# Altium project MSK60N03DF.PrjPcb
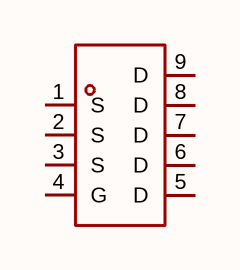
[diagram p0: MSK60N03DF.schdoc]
1 sheet, 1 parts. Net scope: global (net labels, ports and power ports of the same name join across sheets).

## Sheet MSK60N03DF.schdoc
size 127 x 101 mm

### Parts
Q?  msk60n03df  [DFN-8_L3.0-W3.0-P0.65-BL]  (value not drawn)

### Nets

Not connected (* = marked no-connect by the designer): Q? 1(S) 2(S) 3(S) 4(G) 5(D) 6(D) 7(D) 8(D) 9(D)

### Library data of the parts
Q? = msk60n03df: 数量:1个N沟道;漏源电压(Vdss):30V;连续漏极电流(Id):60A;导通电阻(RDS(on)):6mΩ@10V;耗散功率(Pd):59W;阈值电压(Vgs(th)):2.5V;; Manufacturer: MSKSEMI(美森科); AddInBom: yes; ModelId: 8b850663669847e9b39b8fc804d68d4b; ModelName: DFN-8_L3.0-W3.0-H0.7-P0.65; ModelTransform: 118.8974,118.11,0,90,0,0,0,0,0; Number: 1个N沟道; Drain to Source Voltage: 30V; Current - Continuous Drain(Id): 60A; Pd - Power Dissipation: 59W; Gate Threshold Voltage (Vgs(th)): 2.5V; Gate Charge(Qg): 20nC@4.5V; Input Capacitance(Ciss): 2.295nF; Reverse Transfer Capacitance (Crss@Vds): 210pF; Type: N沟道; Output Capacitance(Coss): 267pF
